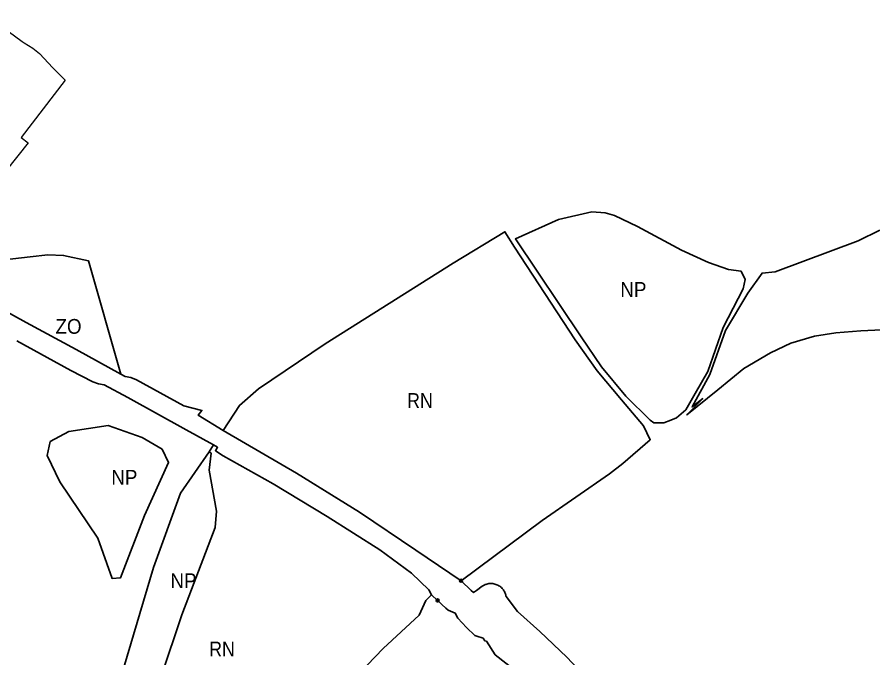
# Model space of a CAD drawing. Extents: x -650276 to -642489, y -1074311 to -1066720.
# Drawn here: x -645941 to -645245, y -1069228 to -1068708 of the extents above; entities that cross this region are included whole.
import ezdxf

# ---------------------------------------------------------------- set-up
doc = ezdxf.new("R2010")
doc.units = 0
doc.header["$LTSCALE"] = 4.8
doc.header["$PDMODE"] = 32
doc.header["$PDSIZE"] = 2.4
for name, color, linetype, lineweight in [('24', 7, 'Continuous', 35), ('42', 7, 'Continuous', 35), ('48', 7, 'Continuous', 35), ('61', 7, 'Continuous', 25), ('7', 7, 'Continuous', 35)]:
    doc.layers.add(name, color=color, linetype=linetype, lineweight=lineweight)
doc.layers.add('62', color=7, linetype='Continuous')

msp = doc.modelspace()

# ---------------------------------------------------------------- linework, layer by layer
at = {"layer": '24'}
for points in [[(-645579.94, -1069165.52), (-645616.63, -1069140.8), (-645662.44, -1069109.89), (-645713.61, -1069078.06), (-645770.04, -1069045.34), (-645773.38, -1069043.46), (-645793.638, -1069031.021), (-645790.53, -1069027.19), (-645805.16, -1069023.52), (-645843.56, -1069002.41), (-645848.18, -1069000.48), (-645852.91, -1068999.62), (-645856.26, -1068997.79), (-645892.77, -1068977.86), (-645933.28, -1068955.74), (-645975.31, -1068932.8)], [(-645940.77, -1068970.74), (-645896.91, -1068994.75), (-645879.17, -1069004.02), (-645874.49, -1069005.73), (-645869.83, -1069006.45), (-645850.79, -1069016.84), (-645803.29, -1069042.92), (-645781.12, -1069055.29), (-645777.73, -1069057.2), (-645779.49, -1069059.92), (-645773.29, -1069063.99), (-645732.65, -1069086.82), (-645688.87, -1069113.44), (-645646.08, -1069140.37), (-645620.2, -1069159.26), (-645606.11, -1069172.98), (-645603.91, -1069176.86), (-645599, -1069181.48)], [(-645571.9, -1069173.43), (-645579.94, -1069165.52), (-645579.94, -1069165.52)], [(-645543.43, -1069178.39), (-645543.547, -1069177.727), (-645543.706, -1069177.053), (-645543.907, -1069176.37), (-645544.154, -1069175.682), (-645544.448, -1069174.993), (-645544.792, -1069174.308), (-645545.186, -1069173.63), (-645545.631, -1069172.966), (-645546.127, -1069172.32), (-645546.674, -1069171.699), (-645547.269, -1069171.107), (-645547.91, -1069170.551), (-645548.594, -1069170.034), (-645549.317, -1069169.563), (-645550.076, -1069169.141), (-645550.863, -1069168.772), (-645551.674, -1069168.459), (-645552.504, -1069168.203), (-645553.344, -1069168.007), (-645554.191, -1069167.87), (-645555.036, -1069167.793), (-645555.875, -1069167.772), (-645556.702, -1069167.808), (-645557.511, -1069167.896), (-645558.298, -1069168.035), (-645559.06, -1069168.219), (-645559.793, -1069168.445), (-645560.494, -1069168.709), (-645561.162, -1069169.007), (-645561.794, -1069169.334), (-645562.39, -1069169.686), (-645562.95, -1069170.06), (-645567.5, -1069173.46), (-645569.81, -1069175.03), (-645571.9, -1069173.43)], [(-645599, -1069181.48), (-645599, -1069181.48), (-645592.24, -1069187.73), (-645590.41, -1069189.45), (-645584.73, -1069191.88), (-645582.63, -1069195.88), (-645575.58, -1069203.57), (-645568.9, -1069209.87), (-645567.07, -1069210.45), (-645562.17, -1069212.02), (-645560.72, -1069214.25), (-645559.33, -1069214.54), (-645552.2, -1069225.59), (-645537.44, -1069237.41)], [(-645230.1, -1069525.98), (-645253.4, -1069493.06), (-645278.31, -1069461.33), (-645281.4, -1069458.4), (-645290.5, -1069449.03), (-645299.61, -1069437.97), (-645306.16, -1069425.55), (-645314.14, -1069412.54), (-645321.1, -1069405.21), (-645326.59, -1069396.64), (-645350.63, -1069363.98), (-645371.12, -1069339.47), (-645376.38, -1069332.65), (-645400.07, -1069313.32), (-645424.8, -1069295.24), (-645458.45, -1069265.56), (-645494.13, -1069227.63), (-645515.89, -1069206.66), (-645534.25, -1069190.56), (-645543.43, -1069178.39)]]:
    msp.add_lwpolyline(points, dxfattribs=at)
for p in [(-645579.94, -1069165.52), (-645599, -1069181.48)]:
    msp.add_point(p, dxfattribs=at)
at = {"layer": '42'}
for points in [[(-645973.36, -1068898.93), (-645954.59, -1068904.41), (-645944.23, -1068904.13), (-645930.1, -1068902.47), (-645915.61, -1068901.02), (-645902.91, -1068901.43), (-645882.63, -1068905.88), (-645856.26, -1068997.79)], [(-645856.26, -1068997.79), (-645892.77, -1068977.86), (-645933.28, -1068955.74), (-645975.31, -1068932.8), (-646017.55, -1068909.75)]]:
    msp.add_lwpolyline(points, dxfattribs=at)
at = {"layer": '48'}
for points in [[(-645349.27, -1068920.83), (-645352.46, -1068914.25), (-645362.84, -1068912.83), (-645379.06, -1068907.27), (-645400.92, -1068897.18), (-645436.72, -1068877.85), (-645455.34, -1068868.9), (-645462.97, -1068866.88), (-645473.89, -1068866.13), (-645500.83, -1068872.25), (-645535.87, -1068888.03), (-645482.49, -1068967.44), (-645466.03, -1068991.95), (-645446.14, -1069015.65), (-645426.36, -1069035.19), (-645423.51, -1069037.41), (-645415.36, -1069037.45), (-645409.61, -1069035.17), (-645405.02, -1069033.34), (-645397.29, -1069026.75), (-645389.73, -1069013.48), (-645379.57, -1068995.66), (-645367.05, -1068959.96), (-645350.93, -1068928.45)], [(-645916.2, -1069063.8), (-645905.94, -1069085.11), (-645874.98, -1069131.01), (-645863.38, -1069163.79), (-645856.76, -1069163.17), (-645837.21, -1069112.54), (-645817.59, -1069069.6), (-645822.85, -1069058.8), (-645838.99, -1069049.31), (-645866.69, -1069039.37), (-645898.57, -1069044.24), (-645913.8, -1069052.51)], [(-645877.15, -1069319.06), (-645877.15, -1069319.06), (-645889.29, -1069330.52), (-645921.56, -1069346.6), (-645935.33, -1069340.64), (-645938.89, -1069341.56), (-645938.399, -1069347.452), (-645933.792, -1069352.53), (-645913.23, -1069356.892), (-645893.291, -1069341.938), (-645867.026, -1069327.317), (-645840.644, -1069294.052), (-645806.806, -1069193.112), (-645779.685, -1069122.296), (-645778.75, -1069108.98), (-645784.52, -1069075.66), (-645783.02, -1069061.84), (-645784.69, -1069060.74), (-645807.89, -1069094.51), (-645829.96, -1069154.65), (-645859.43, -1069254.08), (-645864.96, -1069269.78), (-645867.42, -1069274.21), (-645866.45, -1069276.32)]]:
    msp.add_lwpolyline(points, close=True, dxfattribs=at)
msp.add_lwpolyline([(-645239.85, -1068880.94), (-645257.5, -1068889.68), (-645324.79, -1068914.82), (-645335.45, -1068915.77), (-645346.96, -1068932.01), (-645365.23, -1068962.32), (-645377.9, -1068997.99), (-645392.3, -1069024.38), (-645383.62, -1069017.57), (-645396.53, -1069030.88), (-645371.35, -1069010.64), (-645350.17, -1068993.33), (-645328.55, -1068980.37), (-645311.99, -1068972.74), (-645292.77, -1068966.91), (-645275.45, -1068964.38), (-645255.21, -1068962.49), (-645232.4, -1068961.67), (-645229.27, -1068962.28), (-645189.84, -1068969.91), (-645159.37, -1068981.11), (-645131.73, -1068995.69), (-645122.25, -1068993.21)], dxfattribs=at)
at = {"layer": '61'}
msp.add_lwpolyline([(-645963.52, -1068707.92), (-645936.46, -1068727.71), (-645934.95, -1068728.69), (-645927.9, -1068733.25), (-645922.38, -1068737.4), (-645911.64, -1068749.19), (-645901.71, -1068759.09), (-645937.37, -1068805.77), (-645931.74, -1068810.06), (-645949.45, -1068832.34)], dxfattribs=at)
at = {"layer": '7'}
msp.add_lwpolyline([(-645770.04, -1069045.34), (-645713.61, -1069078.06), (-645694.447, -1069089.98), (-645662.44, -1069109.89), (-645616.63, -1069140.8), (-645579.94, -1069165.52), (-645514.08, -1069116.5), (-645459.5, -1069078.59), (-645448.49, -1069070.45), (-645426.3, -1069051.02), (-645431.85, -1069039.83), (-645449.72, -1069018.58), (-645469.5, -1068995.09), (-645487.38, -1068969.87), (-645536.63, -1068894.79), (-645544.33, -1068882.17), (-645586.28, -1068907.71), (-645690.34, -1068973.16), (-645744.65, -1069009.71), (-645760.07, -1069023.11), (-645773.38, -1069043.46)], close=True, dxfattribs=at)
msp.add_lwpolyline([(-645675.82, -1069254.48), (-645643.34, -1069220.59), (-645613.9, -1069193.45), (-645608.71, -1069181.51), (-645603.91, -1069176.86), (-645606.11, -1069172.98), (-645620.2, -1069159.26), (-645646.08, -1069140.37), (-645688.87, -1069113.44), (-645732.65, -1069086.82), (-645773.29, -1069063.99), (-645779.49, -1069059.92), (-645777.73, -1069057.2), (-645781.12, -1069055.29), (-645784.69, -1069060.74), (-645783.02, -1069061.84), (-645784.52, -1069075.66), (-645778.75, -1069108.98), (-645779.685, -1069122.296), (-645806.806, -1069193.112), (-645840.644, -1069294.052)], dxfattribs=at)

# ---------------------------------------------------------------- texts
at = {"layer": '62'}
for s, width, p in [('NP', 0.95, (-645450.583, -1068935.041)), ('ZO', 0.95, (-645909.476, -1068965.017)), ('RN', 0.9, (-645623.83, -1069025.21)), ('NP', 0.95, (-645864.111, -1069087.517)), ('NP', 0.95, (-645816.111, -1069171.517)), ('RN', 0.9, (-645784.603, -1069226.978))]:
    msp.add_text(s, height=12, dxfattribs=dict(at, width=width)).set_placement(p)

doc.saveas('drawing.dxf')
